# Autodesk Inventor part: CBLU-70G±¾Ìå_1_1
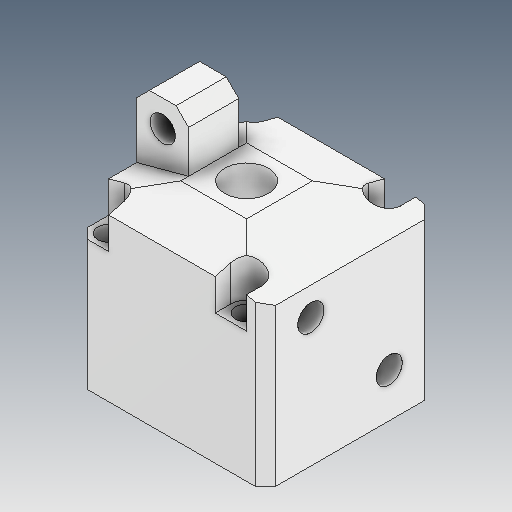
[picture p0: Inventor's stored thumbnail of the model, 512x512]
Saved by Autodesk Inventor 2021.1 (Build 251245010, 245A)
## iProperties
Created: 2021-05
Part Number: CBLU-70G±¾Ìå_1_1
Material: Ogólny
Document SubType Name: Modeling
Designer: user
Density: 1 g/cm^3
Appearance: Domyślna
Author: user
Revision Number: ÈÎºÎ
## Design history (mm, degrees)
feature "ÊäÈë1"
feature "ÊäÈë2"
node "Bryła1"
node "Bryła2"
